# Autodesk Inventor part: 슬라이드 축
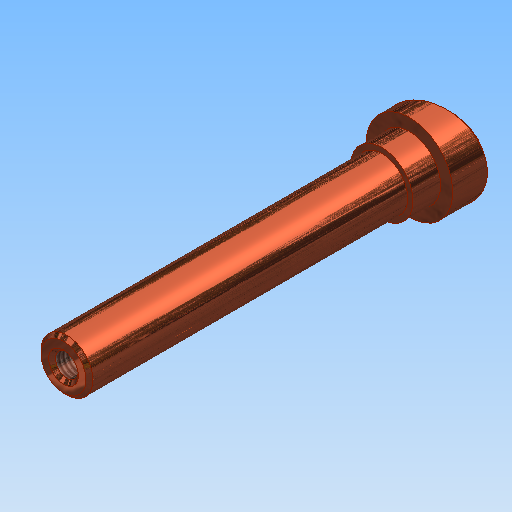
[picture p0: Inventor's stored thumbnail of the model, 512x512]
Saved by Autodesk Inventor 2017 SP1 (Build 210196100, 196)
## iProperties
Created: 2021-07
Part Number: 슬라이드 축
Document SubType Name: 모델링
Designer: mdu
Mass: 21.5729 g
Surface Area: 67.586 cm^2
Volume: 21.5729 cm^3
Density: 1 g/cm^3
Material: 일반
Appearance: 금속 1400F 열
변환 표준: STEP AP214IS
파일 이름: C:\Users\SeoGD\Desktop\?쒗뿕\異?stp
전처리기: Build: 253, Release: 2010 SP1 - Date: Wed 07/29/2009
전송 단위: 밀리미터
불확실성: 0.01
Author: mdu
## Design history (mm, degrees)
sketch "스케치1"
  geometry: L1 (0, 100)-(7.5, 100); L2 (7.5, 100)-(7.5, 0); L3 (7.5, 0)-(12.5, 0); L4 (12.5, 0)-(12.5, -17); L5 (12.5, -17)-(0, -17); L6 (0, -17)-(0, 100); 1 further point
  constraints: 12 end point, 2 parallel, 2 point on line, 1 perpendicular, 1 vertical
  dimensions: "d0" = 100 distance from line of L1 point (0, 0); "d1" = 15 diameter of L2 L6; "d2" = 25 diameter of L4 L6; "d3" = 17 distance of L3.end L4.end
revolve "회전1" sketch "스케치1" stored, may be unused: angle "d4" = 90 deg
sketch "스케치2"
  geometry: L1 (12.5, 0)-(12.5, -17) reference; L2 (-12.5, -17)-(12.5, -17) reference; L3 (-12.5, 0)-(-12.5, -17) reference; L4 (12.5, -5)-(-12.5, -11.699); L5 (-12.5, 0)-(12.5, 0) reference; 1 further point
  constraints: 2 end point, 2 point on line
  dimensions: "d5" = 75 deg angle of L1 L4; "d6" = 5 distance from line of L4.start L5
extrude "돌출1" cut sketch "스케치2" stored distance "d7" = 10; taper "d8" = 0 deg
chamfer "모따기1" distance "d9" = 1; stored, may be unused: second distance "d10" = 2, angle "d11" = 45 deg
fillet "모깎기1" dims "d12" = 0.5
hole "구멍1" diameter "d15" = 6.647; stored, may be unused: countersink angle "d19" = 90 deg, drill point angle "d21" = 118 deg; dims "d13" = 10, "d14" = 10, "d16" = 17, "d17" = 4, "d18" = 2, "d20" = 20
chamfer "모따기2" distance "d22" = 1; stored, may be unused: second distance "d23" = 2, angle "d24" = 45 deg
sketch "스케치3"
  geometry: C1 r 9 at (0, 0); 1 further point
  constraints: 1 centre point, 1 coincident
  dimensions: "d25" = 18 diameter of C1
extrude "돌출2" join sketch "스케치3" distance "d26" = 8; taper "d27" = 0 deg
node "솔리드1"
node "솔리드 본체"
node "곡면 본체"
node "솔리드2"
